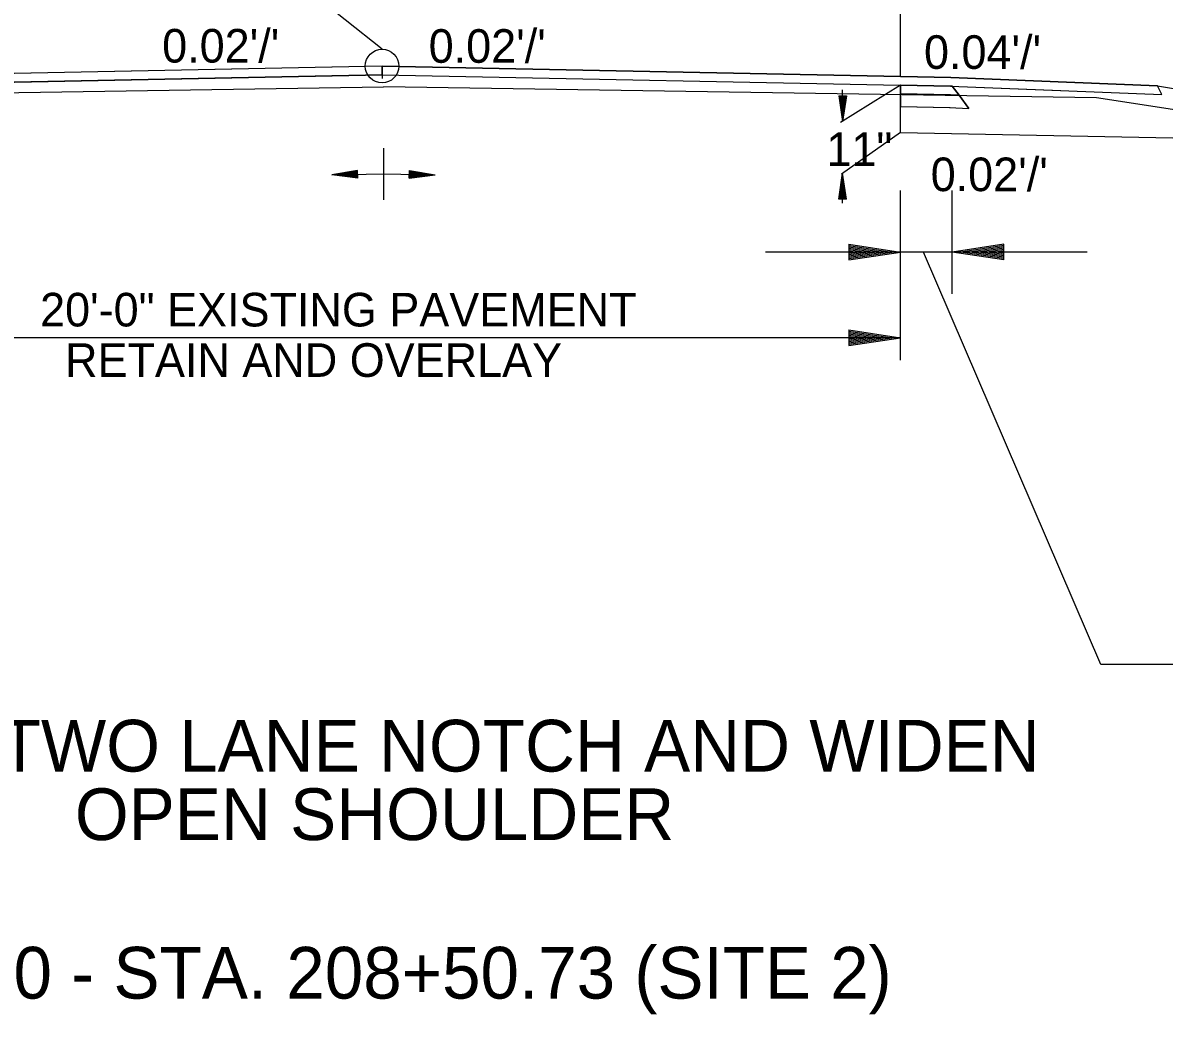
# Model space of a CAD drawing. Extents: x 6848689 to 6848907, y 1900908 to 1901005.
# Drawn here: x 6848739.15 to 6848761.22, y 1900910.15 to 1900929.32 of the extents above; entities that cross this region are included whole.
import ezdxf

# ---------------------------------------------------------------- set-up
doc = ezdxf.new("R2010")
doc.units = 0
for name, color, linetype in [('Default', 7, 'Continuous'), ('R_Draft', 7, 'Continuous'), ('R_No Plot', 7, 'Continuous')]:
    doc.layers.add(name, color=color, linetype=linetype)

msp = doc.modelspace()

# ---------------------------------------------------------------- linework, layer by layer
at = {"layer": 'Default'}
for p, q in [((6848746.097, 1900928.482), (6848735.099, 1900928.262)), ((6848746.097, 1900928.482), (6848757.095, 1900928.262)), ((6848746.097, 1900928.482), (6848746.097, 1900928.315)), ((6848757.095, 1900928.262), (6848746.097, 1900928.482)), ((6848746.097, 1900928.482), (6848746.097, 1900928.242)), ((6848746.097, 1900928.315), (6848746.097, 1900928.482)), ((6848746.097, 1900928.315), (6848735.106, 1900928.095)), ((6848746.097, 1900928.315), (6848757.092, 1900928.095)), ((6848757.095, 1900928.262), (6848761.092, 1900928.102)), ((6848761.092, 1900928.102), (6848757.095, 1900928.262)), ((6848732.33, 1900927.869), (6848746.123, 1900928.082)), ((6848759.916, 1900927.869), (6848746.123, 1900928.082)), ((6848756.124, 1900928.115), (6848756.124, 1900927.948)), ((6848757.092, 1900928.095), (6848756.124, 1900928.115)), ((6848757.092, 1900928.095), (6848759.224, 1900928.01)), ((6848757.124, 1900928.094), (6848757.092, 1900928.095)), ((6848757.124, 1900928.094), (6848757.254, 1900927.922)), ((6848757.254, 1900927.922), (6848757.124, 1900928.094)), ((6848761.092, 1900928.102), (6848771.104, 1900926.433)), ((6848761.177, 1900927.932), (6848761.092, 1900928.102)), ((6848756.124, 1900927.948), (6848757.088, 1900927.929)), ((6848756.124, 1900927.948), (6848756.124, 1900927.698)), ((6848757.082, 1900927.929), (6848757.254, 1900927.922)), ((6848757.254, 1900927.922), (6848757.446, 1900927.664)), ((6848757.446, 1900927.664), (6848757.254, 1900927.922)), ((6848765.919, 1900926.935), (6848759.916, 1900927.869)), ((6848756.124, 1900927.698), (6848757.083, 1900927.679)), ((6848757.072, 1900927.679), (6848757.446, 1900927.664)), ((6848756.124, 1900927.198), (6848767.936, 1900926.961))]:
    msp.add_line(p, q, dxfattribs=at)
for points in [[(6848746.097, 1900928.482), (6848735.099, 1900928.262), (6848731.103, 1900928.102), (6848730.97, 1900927.925), (6848732.97, 1900928.01), (6848735.106, 1900928.095), (6848746.097, 1900928.315)], [(6848746.097, 1900928.315), (6848757.092, 1900928.095), (6848761.177, 1900927.932)], [(6848756.124, 1900927.948), (6848757.088, 1900927.929), (6848757.254, 1900927.922)], [(6848757.254, 1900927.922), (6848757.088, 1900927.929), (6848756.124, 1900927.948)], [(6848756.124, 1900927.698), (6848757.072, 1900927.679), (6848757.446, 1900927.664)]]:
    msp.add_lwpolyline(points, dxfattribs=at)
at = {"layer": 'R_Draft'}
for p, q in [((6848754.928, 1900927.91), (6848755.003, 1900927.41)), ((6848754.928, 1900927.91), (6848755.078, 1900927.91)), ((6848754.94, 1900927.91), (6848755.003, 1900927.493)), ((6848754.953, 1900927.91), (6848755.003, 1900927.579)), ((6848754.965, 1900927.91), (6848755.003, 1900927.662)), ((6848754.978, 1900927.91), (6848755.003, 1900927.747)), ((6848754.991, 1900927.91), (6848755.003, 1900927.831)), ((6848755.003, 1900927.41), (6848755.003, 1900928.022)), ((6848755.078, 1900927.91), (6848755.003, 1900927.41)), ((6848755.027, 1900927.91), (6848755.003, 1900927.747)), ((6848755.052, 1900927.91), (6848755.003, 1900927.579)), ((6848755.065, 1900927.91), (6848755.003, 1900927.493)), ((6848755.04, 1900927.91), (6848755.003, 1900927.662)), ((6848755.014, 1900927.91), (6848755.003, 1900927.831)), ((6848745.623, 1900926.463), (6848745.124, 1900926.378)), ((6848745.626, 1900926.313), (6848745.124, 1900926.378)), ((6848745.623, 1900926.451), (6848745.208, 1900926.38)), ((6848745.625, 1900926.326), (6848745.208, 1900926.38)), ((6848745.623, 1900926.438), (6848745.294, 1900926.382)), ((6848745.625, 1900926.338), (6848745.294, 1900926.382)), ((6848745.623, 1900926.425), (6848745.377, 1900926.383)), ((6848745.625, 1900926.351), (6848745.377, 1900926.383)), ((6848745.624, 1900926.413), (6848745.462, 1900926.385)), ((6848745.625, 1900926.364), (6848745.462, 1900926.385)), ((6848745.624, 1900926.4), (6848745.545, 1900926.387)), ((6848745.624, 1900926.376), (6848745.545, 1900926.387)), ((6848745.626, 1900926.313), (6848745.623, 1900926.463)), ((6848746.622, 1900926.313), (6848746.625, 1900926.463)), ((6848746.622, 1900926.313), (6848747.124, 1900926.378)), ((6848746.623, 1900926.364), (6848746.786, 1900926.385)), ((6848746.623, 1900926.351), (6848746.871, 1900926.383)), ((6848746.623, 1900926.338), (6848746.954, 1900926.382)), ((6848746.623, 1900926.326), (6848747.04, 1900926.38)), ((6848746.624, 1900926.413), (6848746.786, 1900926.385)), ((6848746.624, 1900926.4), (6848746.703, 1900926.387)), ((6848746.624, 1900926.376), (6848746.703, 1900926.387)), ((6848746.625, 1900926.463), (6848747.124, 1900926.378)), ((6848746.625, 1900926.451), (6848747.04, 1900926.38)), ((6848746.625, 1900926.438), (6848746.954, 1900926.382)), ((6848746.625, 1900926.425), (6848746.871, 1900926.383)), ((6848754.928, 1900925.912), (6848755.003, 1900926.412)), ((6848754.94, 1900925.912), (6848755.003, 1900926.328)), ((6848755.003, 1900925.833), (6848755.003, 1900926.412)), ((6848755.078, 1900925.912), (6848755.003, 1900926.412)), ((6848755.065, 1900925.912), (6848755.003, 1900926.328)), ((6848754.953, 1900925.912), (6848755.003, 1900926.242)), ((6848754.965, 1900925.912), (6848755.003, 1900926.159)), ((6848754.978, 1900925.912), (6848755.003, 1900926.074)), ((6848755.052, 1900925.912), (6848755.003, 1900926.242)), ((6848755.04, 1900925.912), (6848755.003, 1900926.159)), ((6848755.027, 1900925.912), (6848755.003, 1900926.074)), ((6848755.078, 1900925.912), (6848754.928, 1900925.912)), ((6848754.991, 1900925.912), (6848755.003, 1900925.991)), ((6848755.014, 1900925.912), (6848755.003, 1900925.991)), ((6848755.124, 1900925.037), (6848756.124, 1900924.887)), ((6848755.124, 1900925.037), (6848755.124, 1900924.737)), ((6848755.124, 1900925.012), (6848755.957, 1900924.887)), ((6848755.124, 1900924.986), (6848755.785, 1900924.887)), ((6848755.124, 1900924.961), (6848755.619, 1900924.887)), ((6848758.124, 1900925.037), (6848757.124, 1900924.887)), ((6848758.124, 1900925.012), (6848757.291, 1900924.887)), ((6848758.124, 1900924.986), (6848757.463, 1900924.887)), ((6848758.124, 1900924.961), (6848757.63, 1900924.887)), ((6848758.124, 1900924.737), (6848758.124, 1900925.037)), ((6848755.124, 1900924.935), (6848755.449, 1900924.887)), ((6848755.124, 1900924.91), (6848755.282, 1900924.887)), ((6848755.124, 1900924.737), (6848756.124, 1900924.887)), ((6848755.124, 1900924.838), (6848755.449, 1900924.887)), ((6848755.124, 1900924.787), (6848755.785, 1900924.887)), ((6848755.124, 1900924.762), (6848755.957, 1900924.887)), ((6848755.124, 1900924.812), (6848755.619, 1900924.887)), ((6848755.124, 1900924.863), (6848755.282, 1900924.887)), ((6848757.124, 1900924.887), (6848756.124, 1900924.887)), ((6848759.999, 1900916.915), (6848756.57, 1900924.887)), ((6848758.124, 1900924.737), (6848757.124, 1900924.887)), ((6848758.124, 1900924.762), (6848757.291, 1900924.887)), ((6848758.124, 1900924.787), (6848757.463, 1900924.887)), ((6848758.124, 1900924.812), (6848757.63, 1900924.887)), ((6848758.124, 1900924.936), (6848757.799, 1900924.887)), ((6848758.124, 1900924.838), (6848757.799, 1900924.887)), ((6848758.124, 1900924.91), (6848757.966, 1900924.887)), ((6848758.124, 1900924.863), (6848757.966, 1900924.887)), ((6848755.124, 1900923.381), (6848756.124, 1900923.231)), ((6848755.124, 1900923.381), (6848755.124, 1900923.081)), ((6848755.124, 1900923.356), (6848755.957, 1900923.231)), ((6848755.124, 1900923.331), (6848755.785, 1900923.231)), ((6848755.124, 1900923.306), (6848755.619, 1900923.231)), ((6848755.124, 1900923.28), (6848755.449, 1900923.231)), ((6848755.124, 1900923.255), (6848755.282, 1900923.231)), ((6848755.124, 1900923.081), (6848756.124, 1900923.231)), ((6848755.124, 1900923.182), (6848755.449, 1900923.231)), ((6848755.124, 1900923.132), (6848755.785, 1900923.231)), ((6848755.124, 1900923.106), (6848755.957, 1900923.231)), ((6848755.124, 1900923.157), (6848755.619, 1900923.231)), ((6848755.124, 1900923.208), (6848755.282, 1900923.231)), ((6848761.422, 1900916.915), (6848759.999, 1900916.915))]:
    msp.add_line(p, q, dxfattribs=at)
msp.add_lwpolyline([(6848746.097, 1900928.807), (6848744.67, 1900929.952), (6848744.426, 1900929.955)], dxfattribs=at)
at = {"layer": 'R_No Plot'}
for p, q in [((6848756.124, 1900928.281), (6848756.124, 1900931.716)), ((6848756.124, 1900928.115), (6848754.961, 1900927.392)), ((6848756.124, 1900927.198), (6848754.983, 1900926.392)), ((6848746.124, 1900926.898), (6848746.124, 1900925.898)), ((6848745.124, 1900926.378), (6848746.124, 1900926.398)), ((6848746.124, 1900926.398), (6848747.124, 1900926.378)), ((6848757.124, 1900924.079), (6848757.124, 1900926.079)), ((6848756.124, 1900924.887), (6848753.514, 1900924.887)), ((6848759.734, 1900924.887), (6848757.124, 1900924.887)), ((6848756.124, 1900923.231), (6848736.124, 1900923.231))]:
    msp.add_line(p, q, dxfattribs=at)
for points in [[(6848756.124, 1900927.198), (6848756.124, 1900928.115)], [(6848756.124, 1900922.798), (6848756.124, 1900926.079)]]:
    msp.add_lwpolyline(points, dxfattribs=at)
msp.add_circle((6848746.097, 1900928.482), 0.325, dxfattribs=at)

# ---------------------------------------------------------------- texts
at = {"layer": 'R_Draft'}
for s, rotation, p in [("0.02'/'", 359.98, (6848741.844, 1900928.55)), ("0.02'/'", 359.98, (6848746.998, 1900928.546)), ("0.04'/'", 359.98, (6848756.577, 1900928.428)), ('11"', 0.02, (6848754.69, 1900926.551)), ("0.02'/'", 359.98, (6848756.707, 1900926.064))]:
    msp.add_text(s, height=0.65, rotation=rotation, dxfattribs=at).set_placement(p)
for s, height, p in [('20\'-0" EXISTING PAVEMENT', 0.65, (6848739.483, 1900923.448)), ('  RETAIN AND OVERLAY', 0.65, (6848739.483, 1900922.473)), ('HWY. 141 - TWO LANE NOTCH AND WIDEN', 1, (6848731.4, 1900914.842)), ('OPEN SHOULDER ', 1, (6848740.156, 1900913.517)), ('STA. 201+59.60 - STA. 208+50.73 (SITE 2)', 1, (6848730.011, 1900910.452))]:
    msp.add_text(s, height=height, dxfattribs=at).set_placement(p)

doc.saveas('drawing.dxf')
